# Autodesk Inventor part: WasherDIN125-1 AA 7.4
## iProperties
Comments: To add or edit properties for Autodesk Inventor files, use iProperties.
Created: 2003-08
Part Number: WasherDIN125-1 AA 7.4
Vendor: Autodesk Inc.
Document SubType Name: Modeling
Designer: FranzK
Material: Default
Description: Washer
Standard: DIN 125
Manufacturer: Standard
Standards Organization: Custom
Alert: To add or edit properties for Autodesk Inventor files, use iProperties.
Control State: 0
Master: False
Checked Out: False
Shininess: 64.0
Length Units: 11269
Angle Units: 11279
Time Units: 11290
Mass Units: 11283
Length Display Precision: 3
Angle Display Precision: 2
Compacted: True
Classification: un/spsc 31161807
Density: 0.0
Volumn: 0.0
Area: 0.0
PropertySet Name: Model Information
Author: FranzK
Revision Number: 5
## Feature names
1. Body [Extrusion]
